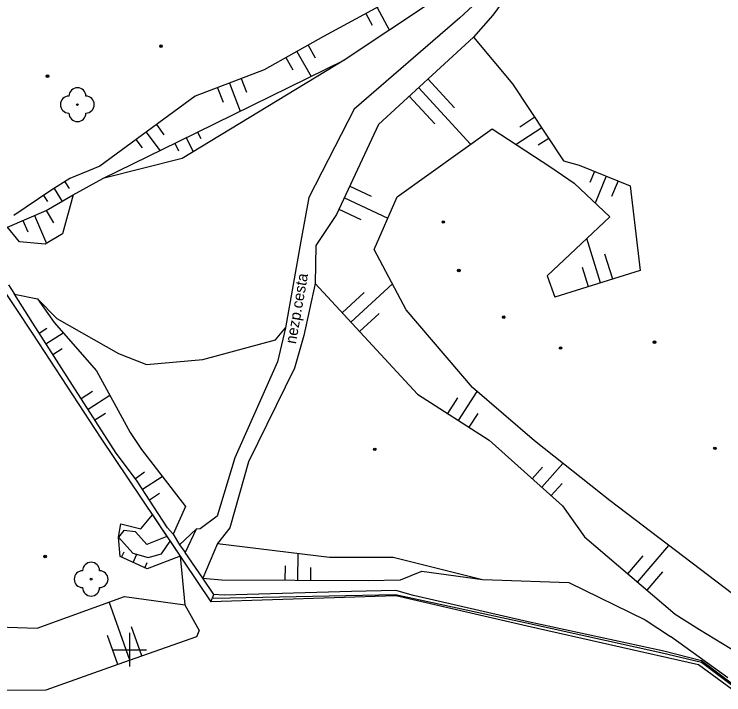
# Model space of a CAD drawing. Extents: x -639440 to -639026, y -1138850 to -1138262.
# Drawn here: x -639256.81 to -639214.88, y -1138602.66 to -1138562.45 of the extents above; entities that cross this region are included whole.
import ezdxf

# ---------------------------------------------------------------- set-up
doc = ezdxf.new("R2010")
doc.units = 0
for name, color, linetype in [('Vrstva 11', 7, 'Continuous'), ('Vrstva 14', 7, 'Continuous'), ('Vrstva 15', 7, 'Continuous'), ('Vrstva 20', 7, 'Continuous'), ('Vrstva 22', 7, 'Continuous'), ('Vrstva 40', 7, 'Continuous'), ('Vrstva 61', 7, 'Continuous'), ('Vrstva 7', 7, 'Continuous')]:
    doc.layers.add(name, color=color, linetype=linetype)

msp = doc.modelspace()

# ---------------------------------------------------------------- linework, layer by layer
at = {"layer": 'Vrstva 11'}
for p, q in [((-639225.11, -1138557.83), (-639228.54, -1138562.51)), ((-639230.49, -1138562.67), (-639229.48, -1138561.73)), ((-639228.54, -1138562.51), (-639229.67, -1138563.8)), ((-639230.49, -1138562.67), (-639236.72, -1138568.05)), ((-639229.67, -1138563.8), (-639235.29, -1138568.96)), ((-639247.1, -1138569.96), (-639237.32, -1138565.16)), ((-639236.72, -1138568.05), (-639239.41, -1138573.28)), ((-639235.29, -1138568.96), (-639237.77, -1138574.29)), ((-639251.58, -1138572.15), (-639247.1, -1138569.96)), ((-639253.33, -1138573.13), (-639251.58, -1138572.15)), ((-639254.92, -1138574.05), (-639253.33, -1138573.13)), ((-639239.41, -1138573.28), (-639239.88, -1138575.86)), ((-639257.22, -1138575.04), (-639254.92, -1138574.05)), ((-639237.77, -1138574.29), (-639238.99, -1138576.11)), ((-639239.88, -1138575.86), (-639240.78, -1138580.98)), ((-639238.99, -1138576.11), (-639239.04, -1138578.36)), ((-639257.16, -1138578.43), (-639256.8, -1138578.99)), ((-639239.04, -1138578.36), (-639239.7, -1138581.43)), ((-639255.72, -1138580.71), (-639256.8, -1138578.99)), ((-639253.36, -1138584.36), (-639255.72, -1138580.71)), ((-639240.78, -1138580.98), (-639241.25, -1138582.99)), ((-639239.7, -1138581.43), (-639240.25, -1138583.36)), ((-639241.25, -1138582.99), (-639243.77, -1138588.66)), ((-639240.25, -1138583.36), (-639242.96, -1138588.89)), ((-639250.79, -1138588.38), (-639253.36, -1138584.36)), ((-639249.58, -1138589.98), (-639250.79, -1138588.38)), ((-639243.77, -1138588.66), (-639244.82, -1138592.11)), ((-639242.96, -1138588.89), (-639244.07, -1138592.79)), ((-639247.75, -1138592.8), (-639249.58, -1138589.98)), ((-639244.82, -1138592.11), (-639245.83, -1138592.85)), ((-639247.42, -1138593.17), (-639247.75, -1138592.8)), ((-639246.07, -1138592.87), (-639246.71, -1138594.26)), ((-639245.83, -1138592.85), (-639246.07, -1138592.87)), ((-639244.07, -1138592.79), (-639244.8, -1138593.72)), ((-639247.42, -1138593.17), (-639247.05, -1138593.8)), ((-639247.05, -1138593.8), (-639246.71, -1138594.26)), ((-639244.8, -1138593.72), (-639245.67, -1138595.78)), ((-639245.67, -1138595.78), (-639246.71, -1138594.26)), ((-639247, -1138594.48), (-639246.73, -1138597.35)), ((-639233.98, -1138595.86), (-639232.73, -1138595.36)), ((-639232.73, -1138595.36), (-639229.14, -1138595.85)), ((-639245.02, -1138596.74), (-639245.67, -1138595.78)), ((-639235.89, -1138595.91), (-639233.98, -1138595.86)), ((-639229.14, -1138595.85), (-639228.56, -1138595.87)), ((-639228.56, -1138595.87), (-639224.05, -1138596.02)), ((-639246.73, -1138597.35), (-639245.88, -1138598.86)), ((-639214.65, -1138601.66), (-639218.03, -1138599.22))]:
    msp.add_line(p, q, dxfattribs=at)
at = {"layer": 'Vrstva 14'}
for p, q in [((-639233.62, -1138561.09), (-639238.53, -1138563.76)), ((-639231.92, -1138561.55), (-639237.32, -1138565.16)), ((-639238.53, -1138563.76), (-639242.04, -1138565.73)), ((-639229.67, -1138563.8), (-639227.37, -1138566.56)), ((-639237.32, -1138565.16), (-639246.89, -1138570.97)), ((-639242.04, -1138565.73), (-639246.13, -1138567.3)), ((-639227.37, -1138566.56), (-639224.35, -1138571.11)), ((-639246.13, -1138567.3), (-639251.75, -1138571.42)), ((-639234.19, -1138573.23), (-639228.58, -1138569.22)), ((-639228.58, -1138569.22), (-639225.11, -1138571.48)), ((-639246.89, -1138570.97), (-639251.58, -1138572.15)), ((-639224.35, -1138571.11), (-639223.44, -1138571.36)), ((-639251.75, -1138571.42), (-639253.52, -1138572.16)), ((-639225.11, -1138571.48), (-639223.73, -1138572.43)), ((-639223.44, -1138571.36), (-639220.42, -1138572.59)), ((-639253.52, -1138572.16), (-639254.65, -1138572.86)), ((-639223.73, -1138572.43), (-639221.61, -1138574.42)), ((-639220.42, -1138572.59), (-639219.83, -1138577.59)), ((-639254.65, -1138572.86), (-639256.83, -1138574.34)), ((-639253.33, -1138573.13), (-639253.96, -1138575.42)), ((-639235.54, -1138576.36), (-639234.19, -1138573.23)), ((-639221.61, -1138574.42), (-639225.33, -1138577.9)), ((-639256.51, -1138575.89), (-639257.22, -1138575.04)), ((-639253.96, -1138575.42), (-639254.98, -1138576.04)), ((-639254.98, -1138576.04), (-639256.51, -1138575.89)), ((-639233.65, -1138579.91), (-639235.54, -1138576.36)), ((-639219.83, -1138577.59), (-639224.86, -1138579.17)), ((-639225.33, -1138577.9), (-639224.86, -1138579.17)), ((-639239.04, -1138578.36), (-639232.98, -1138584.89)), ((-639256.8, -1138578.99), (-639255.44, -1138579.27)), ((-639255.44, -1138579.27), (-639254.46, -1138580.66)), ((-639255.44, -1138579.27), (-639254.29, -1138580.42)), ((-639229.74, -1138584.5), (-639233.65, -1138579.91)), ((-639254.29, -1138580.42), (-639250.66, -1138582.49)), ((-639254.46, -1138580.66), (-639251.95, -1138583.52)), ((-639241.37, -1138581.69), (-639240.78, -1138580.98)), ((-639245.67, -1138582.85), (-639241.37, -1138581.69)), ((-639250.66, -1138582.49), (-639248.99, -1138583.14)), ((-639248.99, -1138583.14), (-639245.67, -1138582.85)), ((-639251.95, -1138583.52), (-639249.96, -1138587.17)), ((-639226.08, -1138587.66), (-639229.74, -1138584.5)), ((-639232.98, -1138584.89), (-639228.74, -1138587.62)), ((-639249.96, -1138587.17), (-639249.3, -1138588.17)), ((-639228.74, -1138587.62), (-639224.42, -1138591.49)), ((-639221.6, -1138591.2), (-639226.08, -1138587.66)), ((-639249.3, -1138588.17), (-639246.7, -1138591.53)), ((-639213.7, -1138597.22), (-639221.6, -1138591.2)), ((-639246.7, -1138591.53), (-639247.42, -1138593.17)), ((-639224.42, -1138591.49), (-639223.11, -1138593.33)), ((-639249.34, -1138592.86), (-639248.65, -1138592.03)), ((-639248.65, -1138592.03), (-639247.79, -1138593.31)), ((-639250.65, -1138593.34), (-639250.51, -1138592.56)), ((-639250.51, -1138592.56), (-639249.34, -1138592.86)), ((-639250.34, -1138592.95), (-639250.65, -1138593.34)), ((-639249.65, -1138593.03), (-639250.34, -1138592.95)), ((-639248.98, -1138593.79), (-639249.65, -1138593.03)), ((-639247.05, -1138593.8), (-639246.07, -1138592.87)), ((-639250.65, -1138593.34), (-639249.81, -1138594.29)), ((-639250.56, -1138594.5), (-639250.65, -1138593.34)), ((-639247.79, -1138593.31), (-639248.98, -1138593.79)), ((-639247.79, -1138593.31), (-639247.6, -1138593.59)), ((-639223.11, -1138593.33), (-639217.76, -1138597.9)), ((-639248.11, -1138594.33), (-639247.6, -1138593.59)), ((-639247.6, -1138593.59), (-639247, -1138594.48)), ((-639244.8, -1138593.72), (-639238.18, -1138594.53)), ((-639249.81, -1138594.29), (-639248.9, -1138594.55)), ((-639248.9, -1138594.55), (-639248.11, -1138594.33)), ((-639248.95, -1138595.22), (-639250.56, -1138594.5)), ((-639247, -1138594.48), (-639248.95, -1138595.22)), ((-639238.18, -1138594.53), (-639234.42, -1138594.54)), ((-639234.42, -1138594.54), (-639229.14, -1138595.85)), ((-639245.67, -1138595.78), (-639244.57, -1138595.87)), ((-639244.57, -1138595.87), (-639235.89, -1138595.91)), ((-639224.05, -1138596.02), (-639219.54, -1138598.23)), ((-639255.46, -1138598.72), (-639250.3, -1138596.85)), ((-639250.3, -1138596.85), (-639246.73, -1138597.35)), ((-639217.76, -1138597.9), (-639216.32, -1138598.81)), ((-639260.24, -1138598.56), (-639255.46, -1138598.72)), ((-639219.54, -1138598.23), (-639218.03, -1138599.22)), ((-639245.88, -1138598.86), (-639246.05, -1138599.23)), ((-639216.32, -1138598.81), (-639214.05, -1138600.18)), ((-639246.05, -1138599.23), (-639250.69, -1138600.87)), ((-639250.69, -1138600.87), (-639254.95, -1138602.39)), ((-639254.95, -1138602.39), (-639260.09, -1138602.42))]:
    msp.add_line(p, q, dxfattribs=at)
at = {"layer": 'Vrstva 15'}
for p, q in [((-639235.374, -1138562.044), (-639234.65, -1138563.375)), ((-639236.033, -1138562.402), (-639235.655, -1138563.098)), ((-639239.45, -1138564.276), (-639239.025, -1138565.033)), ((-639240.758, -1138565.01), (-639240.354, -1138565.731)), ((-639240.104, -1138564.643), (-639239.275, -1138566.12)), ((-639243.401, -1138566.252), (-639243.095, -1138567.049)), ((-639232.366, -1138566.275), (-639230.8, -1138567.981)), ((-639244.101, -1138566.521), (-639243.466, -1138568.176)), ((-639244.801, -1138566.79), (-639244.472, -1138567.649)), ((-639232.918, -1138566.783), (-639229.848, -1138570.127)), ((-639233.471, -1138567.29), (-639231.967, -1138568.928)), ((-639226.06, -1138568.534), (-639226.945, -1138569.121)), ((-639248.41, -1138568.971), (-639247.97, -1138569.571)), ((-639225.645, -1138569.159), (-639227.145, -1138570.155)), ((-639249.015, -1138569.415), (-639248.215, -1138570.505)), ((-639245.982, -1138569.411), (-639245.792, -1138569.799)), ((-639249.62, -1138569.858), (-639249.26, -1138570.349)), ((-639247.329, -1138570.072), (-639247.109, -1138570.521)), ((-639246.655, -1138569.742), (-639246.245, -1138570.578)), ((-639225.23, -1138569.784), (-639225.845, -1138570.192)), ((-639222.524, -1138571.733), (-639222.794, -1138572.394)), ((-639221.83, -1138572.016), (-639222.477, -1138573.606)), ((-639253.818, -1138572.344), (-639253.574, -1138572.737)), ((-639221.135, -1138572.299), (-639221.513, -1138573.227)), ((-639254.455, -1138572.739), (-639253.98, -1138573.506)), ((-639236.99, -1138572.613), (-639235.713, -1138573.207)), ((-639255.081, -1138573.152), (-639254.839, -1138573.508)), ((-639237.306, -1138573.293), (-639234.734, -1138574.49)), ((-639254.919, -1138574.05), (-639254.501, -1138574.772)), ((-639237.623, -1138573.973), (-639236.327, -1138574.576)), ((-639256.297, -1138574.643), (-639256.012, -1138575.305)), ((-639255.608, -1138574.346), (-639254.9, -1138575.991)), ((-639222.165, -1138578.323), (-639222.986, -1138575.707)), ((-639221.449, -1138578.099), (-639221.914, -1138576.619)), ((-639222.88, -1138578.548), (-639223.237, -1138577.412)), ((-639236.919, -1138580.645), (-639234.469, -1138578.372)), ((-639237.429, -1138580.096), (-639236.131, -1138578.891)), ((-639236.409, -1138581.195), (-639235.257, -1138580.126)), ((-639255.345, -1138581.29), (-639254.887, -1138580.993)), ((-639254.938, -1138581.92), (-639253.928, -1138581.266)), ((-639254.531, -1138582.549), (-639253.979, -1138582.193)), ((-639252.856, -1138585.148), (-639252.191, -1138584.723)), ((-639230.559, -1138586.449), (-639229.46, -1138584.742)), ((-639252.452, -1138585.78), (-639251.166, -1138584.958)), ((-639231.19, -1138586.043), (-639230.595, -1138585.119)), ((-639252.048, -1138586.412), (-639251.427, -1138586.015)), ((-639229.928, -1138586.855), (-639229.408, -1138586.046)), ((-639226.204, -1138589.892), (-639225.593, -1138589.21)), ((-639225.646, -1138590.392), (-639224.393, -1138588.993)), ((-639249.651, -1138589.886), (-639249.121, -1138589.486)), ((-639249.236, -1138590.511), (-639248.073, -1138589.756)), ((-639225.087, -1138590.892), (-639224.445, -1138590.176)), ((-639248.827, -1138591.14), (-639248.22, -1138590.745)), ((-639219.985, -1138595.999), (-639218.139, -1138593.838)), ((-639250.471, -1138594.54), (-639250.323, -1138594.209)), ((-639249.786, -1138594.846), (-639249.568, -1138594.359)), ((-639240.046, -1138595.891), (-639240.038, -1138594.303)), ((-639220.555, -1138595.512), (-639219.646, -1138594.447)), ((-639249.101, -1138595.152), (-639248.962, -1138594.84)), ((-639240.796, -1138595.887), (-639240.792, -1138595.049)), ((-639239.296, -1138595.894), (-639239.292, -1138595.144)), ((-639219.415, -1138596.486), (-639218.478, -1138595.39)), ((-639249.983, -1138600.62), (-639251.201, -1138597.176)), ((-639249.276, -1138600.37), (-639249.886, -1138598.646)), ((-639250.69, -1138600.87), (-639251.303, -1138599.153))]:
    msp.add_line(p, q, dxfattribs=at)
at = {"layer": 'Vrstva 20'}
for centre, radius in [((-639248.14, -1138564.34), 0.075), ((-639248.14, -1138564.34), 0.0204), ((-639254.85, -1138566.11), 0.075), ((-639254.85, -1138566.11), 0.0204), ((-639231.46, -1138574.73), 0.075), ((-639231.46, -1138574.73), 0.0204), ((-639230.54, -1138577.59), 0.075), ((-639230.54, -1138577.59), 0.0204), ((-639227.89, -1138580.35), 0.075), ((-639227.89, -1138580.35), 0.0204), ((-639218.98, -1138581.83), 0.075), ((-639218.98, -1138581.83), 0.0204), ((-639224.53, -1138582.17), 0.075), ((-639224.53, -1138582.17), 0.0204), ((-639235.51, -1138588.16), 0.075), ((-639215.41, -1138588.1), 0.075), ((-639215.41, -1138588.1), 0.0204), ((-639235.51, -1138588.16), 0.0204), ((-639254.99, -1138594.49), 0.075), ((-639254.99, -1138594.49), 0.0204)]:
    msp.add_circle(centre, radius, dxfattribs=at)
at = {"layer": 'Vrstva 22'}
for centre in [(-639253.08, -1138567.79), (-639252.27, -1138595.83)]:
    msp.add_circle(centre, 0.05, dxfattribs=at)
for centre, start, end in [((-639253.08, -1138567.29), 0, 180), ((-639253.58, -1138567.79), 90, 270), ((-639252.58, -1138567.79), 270, 90), ((-639253.08, -1138568.29), 180, 0), ((-639252.27, -1138595.33), 0, 180), ((-639252.77, -1138595.83), 90, 270), ((-639251.77, -1138595.83), 270, 90), ((-639252.27, -1138596.33), 180, 0)]:
    msp.add_arc(centre, 0.5, start, end, dxfattribs=at)
at = {"layer": 'Vrstva 61'}
for p, q in [((-639250, -1138599), (-639250, -1138601)), ((-639251, -1138600), (-639249, -1138600))]:
    msp.add_line(p, q, dxfattribs=at)
at = {"layer": 'Vrstva 7'}
for p, q in [((-639259.13, -1138576.22), (-639255.71, -1138581.35)), ((-639255.71, -1138581.35), (-639251.7, -1138587.5)), ((-639251.7, -1138587.5), (-639245.19, -1138597.17)), ((-639245.19, -1138597.17), (-639245.02, -1138596.74)), ((-639234.26, -1138596.82), (-639245.19, -1138597.17)), ((-639234.28, -1138596.76), (-639245.06, -1138596.97)), ((-639244.4, -1138596.77), (-639245.02, -1138596.74)), ((-639236.88, -1138596.56), (-639244.4, -1138596.77)), ((-639234.26, -1138596.5), (-639236.88, -1138596.56)), ((-639226.54, -1138598.43), (-639234.28, -1138596.76)), ((-639233.22, -1138596.79), (-639234.26, -1138596.5)), ((-639226.51, -1138598.61), (-639234.26, -1138596.82)), ((-639226.45, -1138598.36), (-639233.22, -1138596.79)), ((-639218.61, -1138600.19), (-639226.54, -1138598.43)), ((-639218.42, -1138600.09), (-639226.45, -1138598.36)), ((-639216.37, -1138600.89), (-639226.51, -1138598.61)), ((-639216.2, -1138600.75), (-639218.61, -1138600.19)), ((-639216.21, -1138600.66), (-639218.42, -1138600.09)), ((-639190.04, -1138620.41), (-639216.21, -1138600.66)), ((-639210.94, -1138604.92), (-639216.37, -1138600.89)), ((-639210.95, -1138604.73), (-639216.2, -1138600.75))]:
    msp.add_line(p, q, dxfattribs=at)

# ---------------------------------------------------------------- texts
at = {"layer": 'Vrstva 40'}
msp.add_text('nezp.cesta', height=0.65, rotation=80.0303, dxfattribs=at).set_placement((-639240.173, -1138581.959))

doc.saveas('drawing.dxf')
